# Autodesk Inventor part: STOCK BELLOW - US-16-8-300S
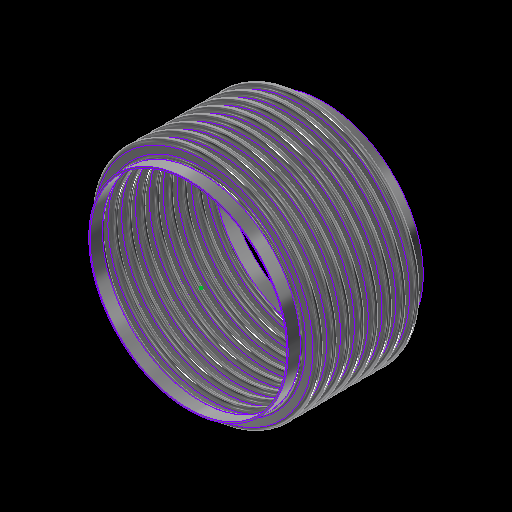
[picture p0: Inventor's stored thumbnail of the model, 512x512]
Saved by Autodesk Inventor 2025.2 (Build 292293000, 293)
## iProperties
Category: 16 GA (0.060 THICK)
RuleStatus: InUse
Created: 2024-01
Part Number: STOCK BELLOW - US-16-8-300S
Project: =STOCK BELLOWS: <Stock Number><SFILL>
Material: ASTM A240-304
Description: =STOCK BELLOWS: <Stock Number>, <SID_> I.D., <SOD_> O.D., <SPLY_> PLY, <Category>, <SNET_CONS> CONS.<PITCH_><STANGENT_> TANGENT<SFILL>
Document SubType Name: Sheet Metal
Designer: GS
Stock Number: U.S-16-8-300S
Surface Area: 17776.9 cm^2
Volume: 2673.35 cm^3
Sheet Metal Rule: Default
Appearance: STAINLESS STEEL
Mass: 21539.9 g
Density: 8.05729 g/cm^3
THK: 0.036
ID: 3.500
OD: 4.250
CONS_: 2
PITCH: 0.500
TANGENT: 0.500
BELLOWS_UPSET: 0.000
d79: 1.000
d82: 1.000
d83: 26.000
d84: 24.000
d174: 8
d214: 8
STHK_: 0.060
SID_: 16.000
SOD_: 18.500
SPITCH_: 1.125
STANGENT__: 1.000
SBELLOWS_UPSET_: 0.000
SDIFF_TAN: 1.000
d252: 2
d275: 2
d287: 0.050
d289: 0.500
d290: 0.000
SOD_NECK: 16 1/4
PLY: 1
PSET: 4.178
PBAR: 1.035
COUNTER: 1.500
NET_TUBE: 3.071
CONS: 2
S_CONS: 0
NET_CONS: 2
ID_M: 88.90 mm
OD_M: 107.95 mm
THK_M: 0.91 mm
ID_U: 3.500 in
OD_U: 4.250 in
THK_U: 0.036 in
TANGENT2: 0.500
TAN_TO_TAN: 1.000 in
d80: 2.571
d81: 10
SID: 2.375
SCONS_: 8
SPITCH: 0.250
STANGENT_: 1.000
SBELLOWS_UPSET: 0.000
SNET_CONS: 8
SS_CONS: 0
SCONS: 8
d190: 8
d191: 1
d192: 1
d193: 8
d194: 0
SIZE: 16.00
PRESSURE: 300
d230: 8
STANGENT: 4.000
SPLY_: 2
d233: 8
d234: 0
d263: 2
d265: 1
d268: 2
d269: 0
d286: 2
d288: 1
d291: 2
d292: 0
SREROLL: 0.750
BLETP: 0.000 ul
PRES_Copy: 85
MATTABLE: 20 GA (0.036 THICK)
PART_NUMBER: U.S-16-8-300S
PITCH_: =, <SPITCH_> PITCH,
CFILL: .
SFILL: .
MESH: ,
COMP: 1.53
EXT: 0.77
LAT: 0.26
ANG: 573
ASR: 9403
LSR: 51812
ANSR: 6104
PRES: 300
COMPM: 15.3
EXTM: 7.65
LATM: 2.60
ASRM: 1646.747
PRESM: 20.684
LSRM: 9073.836
ANSRM: 1068.994
TEMPMIN: 20
TEMPMAX: 800
TEMPMINM: -7
TEMPMAXM: 427
WEIGHTM: 21.540
WEIGHT: 47.487
Author: GS
Keywords: 20 GA (0.036 THICK)
Comments: =STOCK BELLOW - <STOCK NUMBER>
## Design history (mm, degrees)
sketch "Sketch2"
  geometry: L1 (0, -177.245)-(0, 562.856) reference; L2 (45.364, 0)-(44.45, 0); L3 (48.082, -2.718)-(50.343, -2.718); L4 (48.082, -3.632)-(50.343, -3.632); L5 (50.343, -9.982)-(48.082, -9.982); L6 (50.343, -9.068)-(48.082, -9.068); L7 (45.364, -12.7)-(44.45, -12.7); L8 (48.082, 0)-(48.082, -12.7); L9 (50.343, -6.35)-(53.975, -6.35); L10 (44.45, 0)-(44.45, -12.7); L11 (20.376, 102.841)-(20.376, 101.926); L12 (58.262, 457.127)-(58.262, 349.177); L13 (58.262, 444.427)-(58.262, 336.477); L14 (93.133, -58.817)-(93.133, -71.517); L15 (118.746, -66.401)-(118.746, -66.401); L16 (50.343, -9.068)-(50.343, -9.982); L17 (48.082, -9.068)-(48.082, -9.982); L18 (48.082, -9.525)-(50.343, -9.525); L19 (53.975, 0)-(53.975, -12.7); L20 (-50.343, -9.068)-(-50.343, -9.982); L21 (-50.343, -2.718)-(-48.082, -2.718); L22 (-50.343, -3.632)-(-48.082, -3.632); L23 (-48.082, -9.068)-(-50.343, -9.068); L24 (-50.343, -9.525)-(-48.082, -9.525); L25 (-48.082, -9.982)-(-50.343, -9.982); L26 (-48.082, -9.068)-(-48.082, -9.982); L27 (-44.45, 0.653)-(-44.45, -12.047); L28 (-48.082, -6.35)-(-44.45, -6.35); L29 (-50.343, 0.653)-(-50.343, -12.7); L30 (-53.061, 0)-(-53.975, 0); L31 (-53.975, 0)-(-53.975, -12.7); L32 (-53.061, -12.7)-(-53.975, -12.7); A1 r 2.718 centre (48.082, 0) between (45.364, 0) and (48.082, -2.718); A2 r 3.632 centre (48.082, 0) between (44.45, 0) and (48.082, -3.632); A3 r 3.632 centre (50.343, -6.35) between (50.343, -9.982) and (50.343, -2.718); A4 r 2.718 centre (50.343, -6.35) between (50.343, -9.068) and (50.343, -3.632); A5 r 2.718 centre (48.082, -12.7) between (48.082, -9.982) and (45.364, -12.7); A6 r 3.632 centre (48.082, -12.7) between (48.082, -9.068) and (44.45, -12.7); A7 r 3.175 centre (50.343, -6.35) between (50.343, -9.525) and (53.518, -6.35); A8 r 3.175 centre (48.082, -12.7) between (48.082, -9.525) and (44.907, -12.7); A9 r 2.718 centre (-50.343, -12.7) between (-50.343, -9.982) and (-53.061, -12.7); A10 r 2.718 centre (-48.082, -6.35) between (-48.082, -9.068) and (-48.082, -3.632); A11 r 3.175 centre (-48.082, -6.35) between (-48.082, -9.525) and (-44.907, -6.35); A12 r 3.632 centre (-48.082, -6.35) between (-48.082, -9.982) and (-48.082, -2.718); A13 r 3.175 centre (-50.343, -12.7) between (-50.343, -9.525) and (-53.518, -12.7); A14 r 3.632 centre (-50.343, -12.7) between (-50.343, -9.068) and (-53.975, -12.7); A15 r 2.718 centre (-50.343, 0) between (-53.061, 0) and (-50.343, -2.718); A16 r 3.632 centre (-50.343, 0) between (-53.975, 0) and (-50.343, -3.632); 10 further points
  constraints: 62 end point, 38 point on circle, 20 tangent, 16 centre point, 12 parallel, 9 midpoint, 7 vertical, 6 coincident, 6 concentric, 6 point on line, 4 equal radius, 4 perpendicular, 3 horizontal, 1 collinear, 1 horizontal alignment, 10 other
  dimensions: "THK" = 0.9144 distance of L11.start L11.end; "ID" = 88.9 distance of L11.end point (20.376, 13.026); "OD" = 107.95 distance of L12.start L12.end; "PITCH" = 12.7 distance of L12.start L13.start; "TANGENT" = 12.7 distance of L14.start L14.end; "BELLOWS_UPSET" = 0 distance of L15.start L15.end; "d43" = 88.9 diameter of L10 L1 (= ID); "d44" = 107.95 diameter of L9.end L1 (= OD); "d45" = 0.9144 distance between parallel lines of L5 L6 (computed from THK, PLY); "d46" = 3.6322 radius of A3 (computed from PITCH, THK, PLY); "UPSET_PITCH" = 12.7 distance of L2.end L7.end (derived); "SIDEWALL_ANGLE" = 360 deg dimension on L3 L9 (derived); "CON_GAP" = 5.4356 distance of point (48.082, -9.068) point (48.082, -3.632) (derived); "TAN1" = 4.98728 dimension on A8 (derived); "TAN2" = 4.98728 dimension on A7 (derived); "LEG1" = 2.2606 distance of L18.start L18.end (derived); "d278" = 0.9144 distance between parallel lines of L25 L23 (derived); "d279" = 3.6322 radius of A12 (derived); "d280" = 12.7 distance of L30.end L31.end (derived); "d281" = 360 deg dimension on L21 L28 (derived); "d282" = 5.4356 distance of point (-50.343, -9.068) point (-50.343, -3.632) (derived); "d283" = 4.98728 dimension on A13 (derived); "d284" = 4.98728 dimension on A11 (derived); "d285" = 2.2606 distance of L24.start L24.end (derived); "d293" = 88.9 diameter of L27 L1 (derived); "d294" = 107.95 diameter of L31 L1 (derived)
  node "Sketch Rectangular Pattern1" dims "d31" = 25.4, "ID" = 88.9
  node "Sketch Rectangular Pattern2" dims "d39" = 25.4, "PITCH" = 12.7
revolve "CONS" stored, may be unused: angle "d48" = 90 deg
node "BELLOW MIDPLANE"
pattern_linear "Rectangular Pattern2" dims "d52" = 12.7 (= UPSET_PITCH)
sketch "Sketch5"
  geometry: C1 r 45.364 at (0, 0) reference; C2 r 44.45 at (0, 0) reference
extrude "TANGENT" new body sketch "Sketch5" distance "d53" = 12.7 (= TANGENT); taper "d54" = 0 deg
revolve "SAMETAN" stored, may be unused: angle "d65" = 90 deg
revolve "DIFFTAN" stored, may be unused: angle "d70" = 90 deg
sketch "Sketch9"
  geometry: L1 (53.319, 0)-(-53.319, 0) reference; L2 (0, -17.78)-(0, 17.78) reference; L3 (38.085, 0)-(-38.085, 0); L4 (38.085, -11.906)-(38.085, 11.906); L5 (25.385, -11.906)-(25.385, 11.906); L6 (13.15, 11.906)-(13.15, -11.906); L7 (-25.385, -11.906)-(-25.385, 11.906); L8 (-38.085, -11.906)-(-38.085, 11.906); L9 (37.291, -11.906)-(37.291, 11.906); L10 (38.085, -11.906)-(37.291, -11.906); L11 (38.085, 11.906)-(37.291, 11.906); L12 (13.546, 11.906)-(12.753, 11.906); L13 (12.753, 11.906)-(12.753, -11.906); L14 (12.753, -11.906)-(13.546, -11.906); L15 (13.546, -11.906)-(13.546, 11.906); L16 (-13.546, 11.906)-(-13.546, -11.906); L17 (-13.15, 11.906)-(-13.15, -11.906); L18 (-13.546, -11.906)-(-12.753, -11.906); L19 (-12.753, -11.906)-(-12.753, 11.906); L20 (-12.753, 11.906)-(-13.546, 11.906); L21 (-38.085, -11.906)-(-37.291, -11.906); L22 (-37.291, -11.906)-(-37.291, 11.906); L23 (-37.291, 11.906)-(-38.085, 11.906); L24 (-38.085, 11.906)-(-38.085, -11.906); L25 (38.085, -0.397)-(-38.085, -0.397); L26 (-38.085, -0.397)-(-38.085, 0.397); L27 (-38.085, 0.397)-(38.085, 0.397); L28 (38.085, 0.397)-(38.085, -0.397); L29 (-38.085, 11.906)-(38.085, 11.906); L30 (38.085, 11.906)-(38.085, 12.7); L31 (38.085, 12.7)-(-38.085, 12.7); L32 (-38.085, 12.7)-(-38.085, 11.906); L33 (38.085, -11.906)-(-38.085, -11.906); L34 (-38.085, -11.906)-(-38.085, -12.7); L35 (-38.085, -12.7)-(38.085, -12.7); L36 (38.085, -12.7)-(38.085, -11.906); 30 further points
  constraints: 68 end point, 13 midpoint, 13 parallel, 8 horizontal, 7 perpendicular, 6 equal length, 3 point on line, 2 vertical, 14 other
  dimensions: "d115" = 23.8125 distance of L4.start L4.end (derived); "d116" = 12.7 distance between parallel lines of L4 L5 (derived); "d117" = 12.23516 distance between parallel lines of L5 L6 (derived); "d125" = 38.53427 distance between parallel lines of L7 L6 (derived); "d127" = 12.7 distance between parallel lines of L8 L7 (derived); "d128" = 24.93516 distance between parallel lines of L6 L4 (derived); "d130" = 76.16943 distance between parallel lines of L8 L4 (derived); "RULER_THK" = 0.79375 distance between parallel lines of L4 L9; "d135" = 0.79375 distance of L13.end L14.end (derived); "d138" = 26.29911 distance of L13.end L16.end (derived); "d143" = 0.79375 distance of L22.end L8.end (derived); "d144" = 0.79375 distance between parallel lines of L27 L25 (derived)
extrude "RULER" join sketch "Sketch9" distance "d149" = 0.79375 (derived); taper "d150" = 0 deg
extrude "BARS" join sketch "Sketch9" distance "d151" = 0.79375 (derived); taper "d152" = 0 deg
pattern_linear "Rectangular Pattern4" dims "d155" = 26.29911 (derived)
sketch "Sketch13"
  geometry: L1 (93.149, -52.467)-(93.149, -77.867); L2 (206.248, 0)-(203.2, 0); L3 (206.248, -28.575)-(203.2, -28.575); L4 (226.282, -22.955)-(211.868, -22.955); L5 (226.282, -19.907)-(211.868, -19.907); L6 (226.282, -14.287)-(234.95, -14.287); L7 (211.868, -5.62)-(226.282, -5.62); L8 (211.868, 0)-(211.868, -28.575); L9 (203.2, 0)-(203.2, -28.575); L10 (58.254, -26.531)-(58.254, -496.431); L11 (58.254, -55.106)-(58.254, -525.006); L12 (58.254, -112.256)-(58.254, -582.156); L13 (58.254, -140.831)-(58.254, -610.731); L14 (58.254, -169.406)-(58.254, -639.306); L15 (58.254, -197.981)-(58.254, -667.881); L16 (58.254, -226.556)-(58.254, -696.456); L17 (58.254, -83.681)-(58.254, -553.581); L18 (20.376, 103.45)-(20.376, 101.926); L19 (211.868, -8.668)-(226.282, -8.668); L20 (0, -856.437)-(0, 263.431) reference; L21 (-46.99, 0)-(281.94, 0) reference; A1 r 5.62 centre (211.868, 0) between (206.248, 0) and (211.868, -5.62); A2 r 5.62 centre (211.868, -28.575) between (211.868, -22.955) and (206.248, -28.575); A3 r 8.668 centre (211.868, -28.575) between (211.868, -19.907) and (203.2, -28.575); A4 r 5.62 centre (226.282, -14.287) between (226.282, -19.907) and (226.282, -8.668); A5 r 8.668 centre (226.282, -14.287) between (226.282, -22.955) and (226.282, -5.62); A6 r 8.668 centre (211.868, 0) between (203.2, 0) and (211.868, -8.668); 6 further points; 1 other entity
  constraints: 38 end point, 15 point on circle, 9 tangent, 6 centre point, 6 parallel, 5 vertical alignment, 4 point on line, 4 vertical, 3 coincident, 3 concentric, 2 collinear, 2 equal radius, 1 horizontal, 1 perpendicular, 23 other
  dimensions: "SBELLOWS_UPSET_" = 0 distance of point (118.762, -66.401) point (118.762, -66.401); "STOTAL_THK_BELLOW__" = 3.048 distance between parallel lines of L4 L5 (derived); "d224" = 8.66775 radius of A5 (derived); "d225" = 28.575 distance of L2.end L3.end (derived); "SSIDEWALL_ANGLE_" = 360 deg dimension on L7 L6 (derived); "SSCON_GAP_" = 11.2395 distance of point (211.868, -19.907) point (211.868, -8.668) (derived); "d235" = 406.4 diameter of L9 L20 (derived); "d236" = 469.9 diameter of L6.end L20 (derived)
  node "Sketch Rectangular Pattern4" dims "d228" = 25.4
  node "Sketch Rectangular Pattern5" dims "d229" = 25.4
revolve "SBELLOW" stored, may be unused: angle "d197" = 90 deg
pattern_linear "Rectangular Pattern5" dims "d204" = 28.575 (derived)
revolve "STANGENT" stored, may be unused: angle "d240" = 90 deg
revolve "SSAMETAN" stored, may be unused: angle "d241" = 90 deg
revolve "SDIFFTAN" stored, may be unused: angle "d246" = 90 deg
revolve "INVCON" stored, may be unused: angle "d295" = 90 deg
pattern_linear "Rectangular Pattern6" dims "d298" = 12.7 (derived)
revolve "INVTANGENT" stored, may be unused: angle "d302" = 90 deg
revolve "INVSAMETAN" stored, may be unused: angle "d307" = 90 deg
revolve "INVDIFFTAN" stored, may be unused: angle "d312" = 90 deg
sketch "ID BELLOW MOUNT CALC"
  geometry: L1 (44.45, 0)-(38.1, 0); L2 (38.1, 0)-(38.1, 12.7); L3 (38.1, 12.7)-(44.45, 12.7); L4 (44.45, 12.7)-(44.45, 0); L5 (36.513, 12.7)-(35.598, 12.7); L6 (35.598, 12.7)-(35.598, 0); L7 (35.598, 0)-(36.513, 0); L8 (36.513, 0)-(36.513, 12.7); L9 (0, -2.54)-(0, 15.24) reference; L10 (-8.89, 0)-(53.34, 0) reference; 1 further point
  constraints: 16 end point, 5 parallel, 2 collinear, 2 horizontal, 2 perpendicular
  dimensions: "d314" = 12.7 distance of L5.end L6.end (derived); "d315" = 0.9144 distance of L5.start L5.end (derived); "IG" = 1.5875 distance between parallel lines of L2 L8; "PIPE_OD" = 88.9 diameter of L4 L9; "PIPE_WALL" = 6.35 distance of L2.end L3.end; "ID_MT_BELLOW" = 71.1962 diameter of L6 L9 (derived)
revolve "CFILL" stored, may be unused: angle "d320" = 90 deg
pattern_linear "Rectangular Pattern7" dims "d323" = 12.7 (derived)
revolve "SFILL" stored, may be unused: angle "d324" = 90 deg
pattern_linear "Rectangular Pattern8" dims "d327" = 28.575 (derived)
node "STOCK BELLOW MIDPLANE"
node "BELLOW"
sketch "Sketch6"
  geometry: L1 (-12.7, 45.364)-(0, 45.364); L2 (0, 45.364)-(0, 44.45); L3 (0, 44.45)-(-12.7, 44.45); L4 (-12.7, 44.45)-(-12.7, 45.364); L5 (10.16, 0)-(-60.96, 0) reference; L6 (-38.1, -89.422)-(-38.1, 153.44) reference; 1 further point
  constraints: 8 end point, 2 parallel, 1 horizontal, 1 perpendicular
  dimensions: "d61" = 12.7 distance of L2.end L3.end (derived); "d62" = 0.9144 distance of L1.end L2.end (derived); "d63" = 88.9 diameter of L3 L5 (derived); "d64" = 25.4 distance between parallel lines of L4 L6 (derived)
sketch "Sketch12"
  geometry: 1 further point
sketch "Sketch14"
  geometry: L1 (-25.4, 206.248)-(0, 206.248); L2 (0, 206.248)-(0, 203.2); L3 (0, 203.2)-(-25.4, 203.2); L4 (-25.4, 203.2)-(-25.4, 206.248); L5 (5.08, 0)-(-30.48, 0) reference; L6 (0, -41.25)-(0, 247.498) reference; 1 further point
  constraints: 8 end point, 2 parallel, 1 collinear, 1 horizontal, 1 perpendicular
  dimensions: "d237" = 3.048 distance of L3.end L1.start (derived); "d238" = 406.4 diameter of L3 L5 (derived); "d239" = 25.4 distance of L1.start L1.end (derived); "SOD_NECK" = 412.496 diameter of L1 L5 (derived)
sketch "Sketch15"
  geometry: L1 (-41.25, 0)-(247.498, 0) reference; L2 (203.2, -228.6)-(206.248, -228.6); L3 (206.248, -228.6)-(206.248, -254); L4 (206.248, -254)-(203.2, -254); L5 (203.2, -254)-(203.2, -228.6); L6 (0, -307.34)-(0, 66.04) reference; 1 further point
  constraints: 8 end point, 2 parallel, 1 horizontal, 1 perpendicular
  dimensions: "d205" = 25.4 distance of L4.end L2.start (derived); "d206" = 3.048 distance of L3.end L4.end (derived); "d207" = 406.4 diameter of L5 L6 (derived); "d208" = 228.6 distance between parallel lines of L1 L2 (derived)
node "TANGENT_"
node "SAME_TAN"
sketch "Sketch8"
  geometry: L1 (45.364, -25.4)-(44.45, -25.4); L2 (44.45, -25.4)-(44.45, -38.1); L3 (44.45, -38.1)-(45.364, -38.1); L4 (45.364, -38.1)-(45.364, -25.4); L5 (0, -48.26)-(0, 22.86) reference; L6 (-89.422, 0)-(153.44, 0) reference; 1 further point
  constraints: 8 end point, 2 parallel, 1 horizontal, 1 perpendicular
  dimensions: "d66" = 88.9 diameter of L2 L5 (derived); "TOTAL_THK_BELLOW" = 0.9144 distance of L2.end L3.end (derived); "d68" = 25.4 distance between parallel lines of L1 L6 (derived); "d69" = 12.7 distance of L1.end L2.end (derived)
node "DIFF_TAN"
node "Sketch Rectangular Pattern3" dims "d138" = 26.29911 (derived), "d141" = 25.4
node "SBELLOW_"
node "STANGENT_"
node "SSAME_TAN"
sketch "Sketch16"
  geometry: L1 (206.248, -228.6)-(203.2, -228.6); L2 (203.2, -228.6)-(203.2, -254); L3 (203.2, -254)-(206.248, -254); L4 (206.248, -254)-(206.248, -228.6); L5 (0, -307.34)-(0, 66.04) reference; L6 (-41.25, 0)-(247.498, 0) reference; 1 further point
  constraints: 8 end point, 2 parallel, 1 horizontal, 1 perpendicular
  dimensions: "SDIFF_TAN" = 25.4 distance of L3.end L1.start; "d243" = 3.048 distance of L2.end L3.end (derived); "d244" = 228.6 distance between parallel lines of L1 L6 (derived); "d245" = 406.4 diameter of L2 L5 (derived)
node "SDIFF_TAN"
body "Solid15"
sketch "Sketch17"
  geometry: L1 (53.975, 12.7)-(53.061, 12.7); L2 (53.061, 12.7)-(53.061, 0); L3 (53.061, 0)-(53.975, 0); L4 (53.975, 0)-(53.975, 12.7); L5 (0, -2.54)-(0, 15.24) reference; L6 (-10.795, 0)-(64.77, 0) reference; 2 further points
  constraints: 8 end point, 2 parallel, 1 horizontal, 1 midpoint, 1 perpendicular, 1 point on line
  dimensions: "INVTANGENT" = 12.7 distance of L3.end L1.start (derived); "d300" = 0.9144 distance of L1.start L1.end (derived); "d301" = 107.95 diameter of L4 L5 (derived)
body "Solid16"
sketch "Sketch18"
  geometry: L1 (53.975, -25.4)-(53.061, -25.4); L2 (53.061, -25.4)-(53.061, -38.1); L3 (53.061, -38.1)-(53.975, -38.1); L4 (53.975, -38.1)-(53.975, -25.4); L5 (-10.795, 0)-(64.77, 0) reference; L6 (0, -48.26)-(0, 22.86) reference; 1 further point
  constraints: 8 end point, 2 parallel, 1 horizontal, 1 perpendicular
  dimensions: "d303" = 25.4 distance between parallel lines of L1 L5 (derived); "d304" = 12.7 distance of L3.end L1.start (derived); "d305" = 0.9144 distance of L2.end L3.end (derived); "d306" = 107.95 diameter of L4 L6 (derived)
body "Solid17"
sketch "Sketch19"
  geometry: L1 (53.975, -25.4)-(53.061, -25.4); L2 (53.061, -25.4)-(53.061, -38.1); L3 (53.061, -38.1)-(53.975, -38.1); L4 (53.975, -38.1)-(53.975, -25.4); L5 (0, -48.26)-(0, 22.86) reference; L6 (-10.795, 0)-(64.77, 0) reference; 1 further point
  constraints: 8 end point, 2 parallel, 1 horizontal, 1 perpendicular
  dimensions: "d308" = 12.7 distance of L1.end L2.end (derived); "d309" = 107.95 diameter of L4 L5 (derived); "d310" = 0.9144 distance of L2.end L3.end (derived); "d311" = 25.4 distance between parallel lines of L1 L6 (derived)
body "Solid18"
body "Solid19"
body "Solid20"
other parameters: "BMPL" = -114.3, "PSET" = 106.1212 (computed from OD, THK, PLY) [user parameter], "PBAR" = 26.29911 (= 0.570796 x PITCH + OD - ID) [user parameter; used in 1 equation term], "COUNTER" = 15 [user parameter], "NET_TUBE" = 77.99823 (computed from CONS_, PBAR, TANGENT) [user parameter], "S_CONS" = 0 [user parameter; used in 1 equation term], "ID_M" = 88.9 (= ID) [user parameter], "OD_M" = 107.95 (= OD) [user parameter], "THK_M" = 0.9144 (= THK) [user parameter], "ID_U" = 88.9 (= ID) [user parameter], "OD_U" = 107.95 (= OD) [user parameter], "THK_U" = 0.9144 (= THK) [user parameter], "D_UNITS" = 0 [user parameter], "TANGENT2" = 12.7 [user parameter], "TAN_TO_TAN" = 25.4 [user parameter], "OD_NECK" = 90.7288 [user parameter], "d79" = 25.4, "d80" = 65.29823 [user parameter], "d82" = 25.4, "d83" = 660.4, "d84" = 609.6, "sa_0" = 4, "FRAME_THK" = 0.79375 [user parameter], "CON_FLAT" = 12.23516 [user parameter], "SID" = 60.325 [user parameter], "SPITCH" = 6.35 [user parameter], "STANGENT_" = 25.4 [user parameter], "SBELLOWS_UPSET" = 0 [user parameter], "SS_CONS" = 0 [user parameter], "STAN_TO_TAN_" = 228.6 [user parameter], "d100" = 3.048 [user parameter], "d191" = 25.4 [user parameter], "d194" = 0 [user parameter], "STANGENT" = 101.6 [user parameter], "d234" = 0 [user parameter], "SUPSET_PITCH_" = 28.575 [user parameter], "d269" = 0 [user parameter], "d287" = 1.27, "d289" = 12.7, "d290" = 0, "d292" = 0 [user parameter], "Thickness" = 3.048 (derived), "KFactor" = 4.4, "BendRadius" = 3.048 (derived), "BendReliefWidth" = 3.048 (derived), "BendReliefDepth" = 1.524 (derived), "CornerReliefSize" = 12.192 (derived), "SeamGap" = 0.00508, "MinimumRemnant" = 6.096 (derived), "TransitionRadius" = 3.048 (derived), "JacobiRadiusSize" = 3.048 (derived), "GapSize" = 3.048 (derived), "SREROLL" = 19.05 [user parameter], "CUR_STK_PITCH" = 28.575 [user parameter], "d328" = -114.3 (derived), "ASR" = 94030 [user parameter], "LSR" = 518120 [user parameter], "ANSR" = 61040 [user parameter], "BLETP" = 0 [user parameter], "ASRM" = 16467.4739 [user parameter], "PRESM" = 206.83949 [user parameter], "LSRM" = 90738.3556 [user parameter], "ANSRM" = 10689.9352 [user parameter], "TEMPMIN" = 2664.83333 [user parameter], "TEMPMAX" = 6998.16667 [user parameter], "TEMPMINM" = 2664.83333 [user parameter], "TEMPMAXM" = 6998.16667 [user parameter], "WEIGHT" = 215.39929 [user parameter], "WEIGHTM" = 0.2154 [user parameter]
